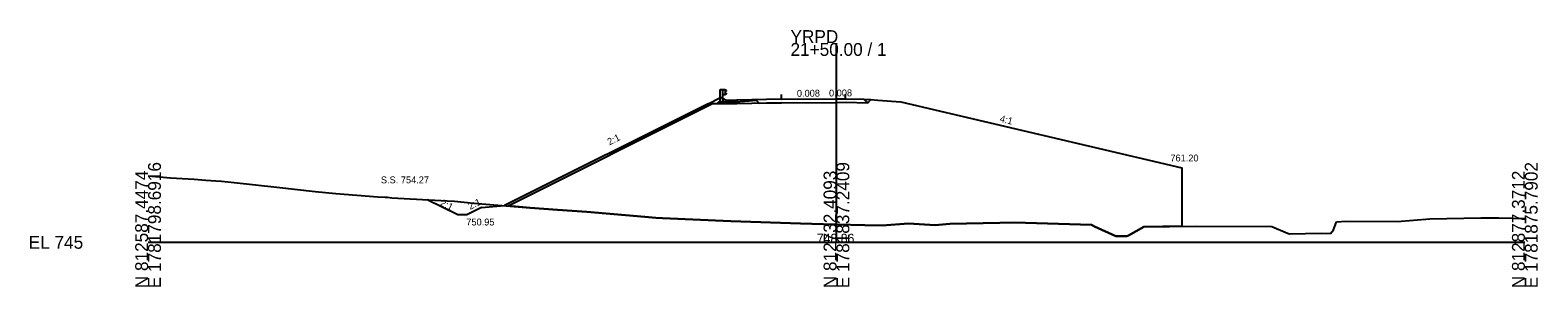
# Model space of a CAD drawing. Extents: x -26 to 1403, y -10 to 9544.
# Drawn here: x 974.3 to 1302.8, y 1490.3 to 1546.2 of the extents above; entities that cross this region are included whole.
import ezdxf

# ---------------------------------------------------------------- set-up
doc = ezdxf.new("R2010")
doc.units = 0
for name, color, linetype in [('Exist Cross Section Cell', 7, 'Continuous'), ('Exist XS Center Line Elevation Label', 7, 'Continuous'), ('Exist XS Ground Line', 7, 'Continuous'), ('Prop XS DDE', 7, 'Continuous'), ('Prop XS Ditch Standard Text', 7, 'Continuous'), ('Prop XS Dump Level', 7, 'Continuous'), ('Prop XS Earthwork Shape', 7, 'Continuous'), ('Prop XS EOT Tick Mark', 7, 'Continuous'), ('Prop XS Finish Grade', 7, 'Continuous'), ('Prop XS Finish Grade CurbGutter', 7, 'Continuous'), ('Prop XS Finish Grade Earthwork', 7, 'Continuous'), ('Prop XS Finish Grade Paved Shoulder', 7, 'Continuous'), ('Prop XS Finish Grade Pavement', 7, 'Continuous'), ('Prop XS Guardrail', 7, 'Continuous'), ('Prop XS Pvmt Edge Slope', 7, 'Continuous'), ('Prop XS SE Text', 7, 'Continuous'), ('Prop XS Side Slope Text', 7, 'Continuous'), ('Prop XS SS Elevation Text', 7, 'Continuous'), ('Prop XS Subgrade CurbGutter', 7, 'Continuous'), ('Prop XS Subgrade Earthwork', 7, 'Continuous')]:
    doc.layers.add(name, color=color, linetype=linetype)

msp = doc.modelspace()

# ---------------------------------------------------------------- linework, layer by layer
at = {"layer": 'Exist Cross Section Cell'}
for p, q in [((1150, 1500), (1150, 1543.4)), ((1000, 1500), (1150, 1500)), ((1150, 1500), (1300, 1500))]:
    msp.add_line(p, q, dxfattribs=at)
at = {"layer": 'Exist XS Ground Line'}
for p, q in [((1000, 1514.47), (1004.91, 1514.04)), ((1004.91, 1514.04), (1008.75, 1513.84)), ((1008.75, 1513.84), (1010.02, 1513.72)), ((1010.02, 1513.72), (1012.59, 1513.5)), ((1012.59, 1513.5), (1014.77, 1513.36)), ((1014.77, 1513.36), (1015.97, 1513.33)), ((1015.97, 1513.33), (1018.77, 1513.01)), ((1018.77, 1513.01), (1028.06, 1512.02)), ((1028.06, 1512.02), (1036.4, 1511.09)), ((1036.4, 1511.09), (1040.88, 1510.63)), ((1040.88, 1510.63), (1050.07, 1509.94)), ((1050.07, 1509.94), (1051.66, 1509.84)), ((1051.66, 1509.84), (1052.17, 1509.81)), ((1052.17, 1509.81), (1053.13, 1509.7)), ((1053.13, 1509.7), (1065.2, 1509.02)), ((1065.2, 1509.02), (1066.81, 1508.93)), ((1066.81, 1508.93), (1071.02, 1508.54)), ((1071.02, 1508.54), (1083.25, 1507.53)), ((1083.25, 1507.53), (1089.22, 1507.08)), ((1089.22, 1507.08), (1095.62, 1506.63)), ((1095.62, 1506.63), (1108.24, 1505.58)), ((1108.24, 1505.58), (1110.65, 1505.32)), ((1110.65, 1505.32), (1112.12, 1505.25)), ((1112.12, 1505.25), (1127.02, 1504.64)), ((1272.2, 1504.5), (1279.3, 1505.09)), ((1279.3, 1505.09), (1290.44, 1505.35)), ((1290.44, 1505.35), (1294.35, 1505.32)), ((1294.35, 1505.32), (1300, 1505.2)), ((1127.02, 1504.64), (1142.19, 1504.12)), ((1142.19, 1504.12), (1147.1, 1503.92)), ((1147.1, 1503.92), (1150, 1503.86)), ((1150, 1503.86), (1156.22, 1503.72)), ((1156.22, 1503.72), (1159.94, 1503.66)), ((1159.94, 1503.66), (1165.68, 1504.11)), ((1165.68, 1504.11), (1171.5, 1503.72)), ((1171.5, 1503.72), (1174.73, 1503.99)), ((1174.73, 1503.99), (1185.61, 1504.25)), ((1185.61, 1504.25), (1188.82, 1504.31)), ((1188.82, 1504.31), (1205.55, 1503.8)), ((1205.55, 1503.8), (1206.22, 1503.48)), ((1206.22, 1503.48), (1210.89, 1501.31)), ((1213.28, 1501.37), (1213.64, 1501.48)), ((1213.64, 1501.48), (1217.01, 1503.39)), ((1217.01, 1503.39), (1228.15, 1503.53)), ((1228.15, 1503.53), (1244.88, 1503.45)), ((1244.88, 1503.45), (1248.32, 1502.02)), ((1248.32, 1502.02), (1248.69, 1501.88)), ((1248.69, 1501.88), (1255.62, 1501.99)), ((1255.62, 1501.99), (1257.69, 1501.95)), ((1257.69, 1501.95), (1258.28, 1502.75)), ((1258.28, 1502.75), (1259, 1504.44)), ((1259, 1504.44), (1261.08, 1504.63)), ((1261.08, 1504.63), (1272.2, 1504.5)), ((1210.89, 1501.31), (1212.34, 1501.31)), ((1212.34, 1501.31), (1213.28, 1501.37))]:
    msp.add_line(p, q, dxfattribs=at)
at = {"layer": 'Prop XS DDE'}
for p, q in [((1067.47, 1505.95), (1060.84, 1509.27)), ((1072.69, 1507.57), (1077.69, 1507.99)), ((1069.47, 1505.95), (1067.47, 1505.95)), ((1072.69, 1507.57), (1069.47, 1505.95))]:
    msp.add_line(p, q, dxfattribs=at)
at = {"layer": 'Prop XS Dump Level'}
for p, q in [((1138, 1531.16), (1150, 1531.26)), ((1150, 1531.26), (1152, 1531.28))]:
    msp.add_line(p, q, dxfattribs=at)
at = {"layer": 'Prop XS Earthwork Shape'}
msp.add_lwpolyline([(1159, 1530.96), (1164, 1530.56), (1225.28, 1516.2), (1225.28, 1503.49), (1217.01, 1503.39), (1213.64, 1501.48), (1213.28, 1501.37), (1212.34, 1501.31), (1210.89, 1501.31), (1206.22, 1503.48), (1205.55, 1503.8), (1188.82, 1504.31), (1185.61, 1504.25), (1174.73, 1503.99), (1171.5, 1503.72), (1165.68, 1504.11), (1159.94, 1503.66), (1156.22, 1503.72), (1150, 1503.86), (1147.1, 1503.92), (1142.19, 1504.12), (1127.02, 1504.64), (1112.12, 1505.25), (1110.65, 1505.32), (1108.24, 1505.58), (1095.62, 1506.63), (1089.22, 1507.08), (1083.25, 1507.53), (1078.45, 1507.92), (1123, 1530.2), (1131, 1530.84), (1132.5, 1530.96), (1133.19, 1530.27), (1138.01, 1530.37), (1150.01, 1530.47), (1152, 1530.49), (1156.81, 1530.39), (1157.5, 1531.08)], close=True, dxfattribs=at)
at = {"layer": 'Prop XS EOT Tick Mark'}
for p, q in [((1138, 1531.16), (1138, 1532.16)), ((1152, 1531.28), (1152, 1532.28))]:
    msp.add_line(p, q, dxfattribs=at)
at = {"layer": 'Prop XS Finish Grade'}
for p, q in [((1122.07, 1530.17), (1124.73, 1531.51)), ((1125.31, 1531.22), (1124.73, 1531.51)), ((1156, 1531.2), (1157.5, 1531.08))]:
    msp.add_line(p, q, dxfattribs=at)
at = {"layer": 'Prop XS Finish Grade CurbGutter'}
for p, q in [((1126, 1530.88), (1125.31, 1531.22)), ((1128.33, 1530.97), (1126, 1530.88))]:
    msp.add_line(p, q, dxfattribs=at)
at = {"layer": 'Prop XS Finish Grade Earthwork'}
for p, q in [((1157.5, 1531.08), (1159, 1530.96)), ((1122.07, 1530.17), (1077.69, 1507.99)), ((1159, 1530.96), (1164, 1530.56)), ((1164, 1530.56), (1225.28, 1516.2)), ((1225.28, 1516.2), (1225.28, 1503.49))]:
    msp.add_line(p, q, dxfattribs=at)
at = {"layer": 'Prop XS Finish Grade Paved Shoulder'}
for p, q in [((1138, 1531.16), (1128.33, 1530.97)), ((1152, 1531.28), (1156, 1531.2))]:
    msp.add_line(p, q, dxfattribs=at)
at = {"layer": 'Prop XS Finish Grade Pavement'}
for p, q in [((1138, 1531.16), (1150, 1531.26)), ((1150, 1531.26), (1152, 1531.28))]:
    msp.add_line(p, q, dxfattribs=at)
at = {"layer": 'Prop XS Guardrail'}
for p, q in [((1124.68, 1533.27), (1125.18, 1533.27)), ((1124.68, 1530.77), (1124.68, 1533.27)), ((1125.18, 1533.27), (1125.68, 1533.27)), ((1125.18, 1533.27), (1125.18, 1530.77)), ((1125.68, 1532.14), (1125.18, 1532.14)), ((1125.68, 1533.27), (1125.97, 1533.07)), ((1125.97, 1532.95), (1125.68, 1532.75)), ((1125.68, 1532.75), (1125.68, 1532.66)), ((1125.68, 1532.66), (1125.97, 1532.46)), ((1125.97, 1532.34), (1125.68, 1532.14)), ((1125.97, 1533.07), (1126, 1533.01)), ((1126, 1533.01), (1125.97, 1532.95)), ((1125.97, 1532.46), (1126, 1532.4)), ((1126, 1532.4), (1125.97, 1532.34))]:
    msp.add_line(p, q, dxfattribs=at)
at = {"layer": 'Prop XS Pvmt Edge Slope'}
for p, q in [((1156, 1531.2), (1156.81, 1530.39)), ((1124.31, 1530.55), (1123.94, 1530.17)), ((1125.31, 1530.55), (1124.31, 1530.55))]:
    msp.add_line(p, q, dxfattribs=at)
at = {"layer": 'Prop XS Subgrade CurbGutter'}
for p, q in [((1125.31, 1530.55), (1125.31, 1531.22)), ((1128.33, 1530.97), (1128.33, 1530.55)), ((1128.33, 1530.55), (1125.31, 1530.55))]:
    msp.add_line(p, q, dxfattribs=at)
at = {"layer": 'Prop XS Subgrade Earthwork'}
for p, q in [((1156.81, 1530.39), (1157.5, 1531.08)), ((1123.94, 1530.17), (1122.07, 1530.17)), ((1128.33, 1530.17), (1123.94, 1530.17)), ((1138, 1530.37), (1128.33, 1530.18)), ((1128.33, 1530.18), (1128.33, 1530.17)), ((1138.01, 1530.37), (1150.01, 1530.47)), ((1150.01, 1530.47), (1152, 1530.49)), ((1152, 1530.49), (1156.81, 1530.39))]:
    msp.add_line(p, q, dxfattribs=at)

# ---------------------------------------------------------------- texts
at = {"layer": 'Exist Cross Section Cell'}
for s, p in [('YRPD', (1140, 1543.4)), ('21+50.00 / 1', (1140, 1540.6)), ('EL 745', (974, 1498.6))]:
    msp.add_text(s, height=2.8, dxfattribs=at).set_placement(p)
for s, p in [('N 812587.4474', (1000, 1490)), ('E 1781798.6916', (1002.8, 1490)), ('N 812732.4093', (1150, 1490)), ('E 1781837.2409', (1152.8, 1490)), ('N 812877.3712', (1300, 1490)), ('E 1781875.7902', (1302.8, 1490))]:
    msp.add_text(s, height=2.8, rotation=90, dxfattribs=at).set_placement(p)
at = {"layer": 'Exist XS Center Line Elevation Label'}
msp.add_text('748.86', height=2, dxfattribs=at).set_placement((1145.73, 1499.86))
at = {"layer": 'Prop XS Ditch Standard Text'}
for s, p in [('761.20', (1222.77, 1517.61)), ('750.95', (1069.35, 1503.67))]:
    msp.add_text(s, height=1.5, dxfattribs=at).set_placement(p)
at = {"layer": 'Prop XS Dump Level'}
for s, p in [('Case2', (1128.33, 1530.93)), ('Case4', (1126, 1530.4)), ('Case4', (1164, 1530.52))]:
    msp.add_text(s, height=0.04, dxfattribs=at).set_placement(p)
at = {"layer": 'Prop XS SE Text'}
for p in [(1141.39, 1531.69), (1148.39, 1531.75)]:
    msp.add_text('0.008', height=1.5, rotation=0.4834, dxfattribs=at).set_placement(p)
at = {"layer": 'Prop XS Side Slope Text'}
for s, rotation, p in [('4:1', 345.9638, (1185.5, 1526.28)), ('2:1', 26.5651, (1100.54, 1521.09)), ('2:1', 333.4349, (1063.51, 1508.11)), ('2:1', 26.5651, (1070.21, 1507.07))]:
    msp.add_text(s, height=1.5, rotation=rotation, dxfattribs=at).set_placement(p)
at = {"layer": 'Prop XS SS Elevation Text'}
msp.add_text('S.S. 754.27', height=1.5, dxfattribs=at).set_placement((1050.73, 1512.85))

doc.saveas('drawing.dxf')
